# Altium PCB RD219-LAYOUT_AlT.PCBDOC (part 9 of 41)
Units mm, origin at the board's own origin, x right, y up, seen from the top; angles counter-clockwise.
Board outline 209.75 x 159.97 mm, 2 copper layers (TOP, BOTTOM), stack 0 mm thick; 398 components, 199 nets, 1469 pads, 0 vias.
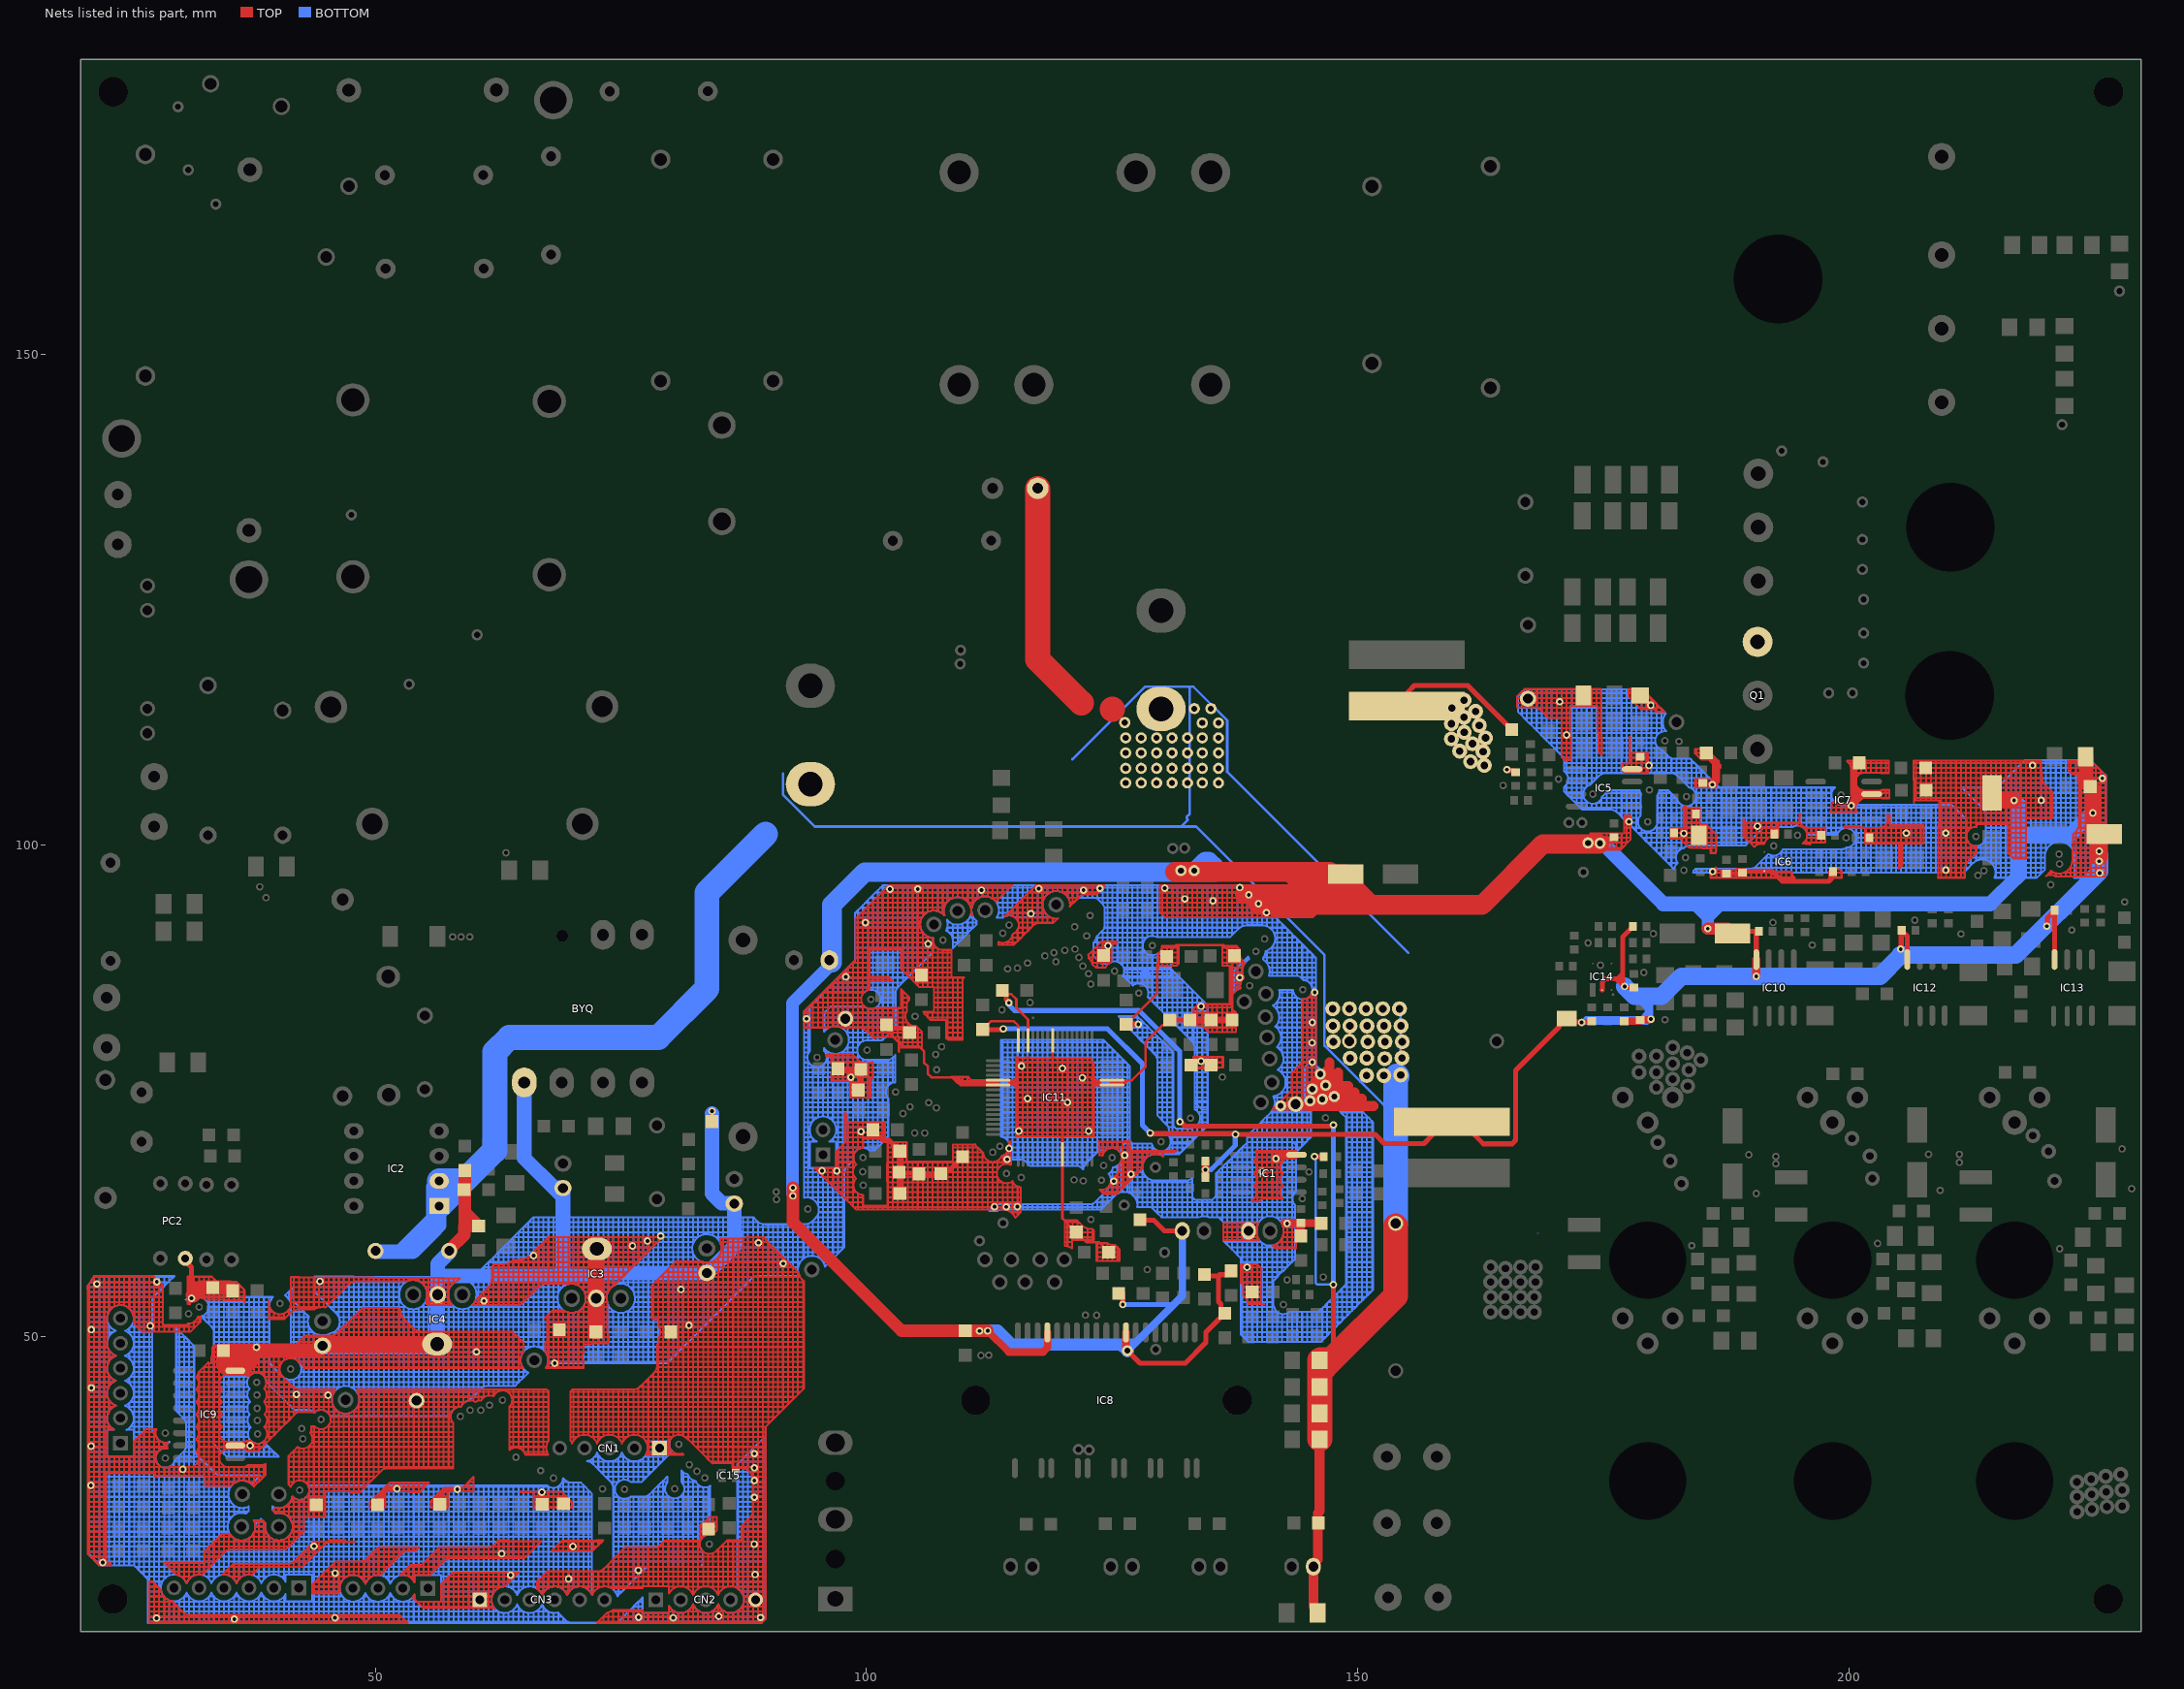
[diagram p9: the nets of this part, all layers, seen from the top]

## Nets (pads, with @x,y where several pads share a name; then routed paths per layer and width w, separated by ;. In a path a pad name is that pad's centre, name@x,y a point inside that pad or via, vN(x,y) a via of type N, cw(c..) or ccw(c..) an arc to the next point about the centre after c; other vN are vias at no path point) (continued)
GND: (continued)
  TOP w0.203: 69.149,48.956 69.657,48.956 ; 69.149,49.464 69.149,49.972 ; 69.149,49.464 69.657,49.464 ; 69.149,49.972 C83.2@69.149,50.48 ; 69.149,49.972 69.657,49.972 ; C83.2@69.149,50.48 69.657,50.48 ; C83.2@69.149,50.48 C83.2@69.149,50.988 ; C83.2@69.149,50.988 69.149,51.496 ; C83.2@69.149,50.988 69.657,50.988 ; 69.149,51.496 69.149,52.004 ; 69.149,51.496 69.657,51.496 ; 69.149,52.004 69.149,52.512 ; 69.149,52.004 69.657,52.004 ; 69.149,52.512 69.149,52.684 ; 69.149,52.512 69.483,52.512 ; 69.149,52.684 69.161,52.684 ; 69.149,55.388 69.657,55.388 ; 69.149,55.388 69.149,55.56 ; 69.149,55.56 69.149,56.068 ; 69.149,55.56 69.657,55.56 ; 69.149,56.068 69.657,56.068 ; 69.149,56.068 69.149,56.576 ; 69.149,56.576 69.657,56.576 ; 69.149,56.576 69.149,57.084 ; 69.149,57.084 69.657,57.084 ; 69.149,57.084 69.149,57.592 ; 69.149,57.592 69.149,58.1 ; 69.149,57.592 69.657,57.592 ; 69.149,58.1 69.149,58.608 ; 69.149,58.1 69.657,58.1 ; 69.149,58.608 69.657,58.608 ; 69.149,58.608 69.149,59.116 ; 69.149,59.116 69.657,59.116 ; 69.149,59.116 69.149,59.624 ; 69.149,59.624 69.657,59.624 ; 69.149,59.624 69.149,60.132 ; 69.149,60.132 69.657,60.132 ; 69.161,52.684 ccw(c69.991,53.846) 69.483,52.512 ; 69.483,52.512 ccw(c69.991,53.846) 69.657,52.458 ; 69.503,33.716 R80.1@69.657,33.562 ; 69.657,23.962 cw(c70.8,23.241) 69.728,24.064 ; 69.657,23.962 69.657,24.064 ; 69.657,24.064 69.657,24.572 ; 69.657,24.064 69.728,24.064 ; 69.657,24.572 pad.@69.657,25.08 ; 69.657,24.572 70.165,24.572 ; pad.@69.657,25.08 pad.@69.657,25.588 ; pad.@69.657,25.08 70.165,25.08 ; pad.@69.657,25.588 69.657,26.096 ; pad.@69.657,25.588 70.165,25.588 ; 69.657,26.096 69.657,26.129 ; 69.657,26.096 70.165,26.096 ; 69.657,26.129 70.165,26.129 ; 69.657,28.222 69.657,28.636 ; 69.657,28.222 70.165,28.222 ; 69.657,28.636 pad.@70.165,28.636 ; 69.657,28.636 69.657,29.144 ; 69.657,29.144 70.165,29.144 ; 69.657,29.144 69.657,29.244 ; R80.1@69.657,32.596 R80.1@69.657,32.7 ; R80.1@69.657,32.596 70.016,32.596 70.016,32.7 ; R80.1@69.657,32.7 70.016,32.7 ; R80.1@69.657,32.7 R80.1@69.657,33.208 ; R80.1@69.657,33.208 70.011,33.208 ; R80.1@69.657,33.208 R80.1@69.657,33.562 ; R80.1@69.657,33.562 70.011,33.208 ; 69.657,46.838 70.165,46.838 ; 69.657,46.838 69.657,46.924 ; 69.657,46.924 70.165,46.924 ; 69.657,46.924 69.657,47.432 ; 69.657,47.432 70.165,47.432 ; 69.657,47.432 69.657,47.94 ; 69.657,47.94 69.657,48.448 ; 69.657,47.94 70.165,47.94 ; 69.657,48.448 69.657,48.956 ; 69.657,48.448 70.165,48.448 ; 69.657,48.956 69.657,49.464 ; 69.657,48.956 70.165,48.956 ; 69.657,49.464 69.657,49.972 ; 69.657,49.464 70.165,49.464 ; 69.657,49.972 69.657,50.48 ; 69.657,49.972 70.165,49.972 ; 69.657,50.48 69.657,50.988 ; 69.657,50.48 70.165,50.48 ; 69.657,50.988 69.657,51.496 ; 69.657,50.988 70.165,50.988 ; 69.657,51.496 69.657,52.004 ; 69.657,51.496 70.165,51.496 ; 69.657,52.004 70.165,52.004 ; 69.657,52.004 69.657,52.458 ; 69.657,52.458 ccw(c69.991,53.846) 70.165,52.429 ; 69.657,55.388 69.657,55.56 ; 69.657,55.388 69.806,55.388 ; 69.657,55.56 69.657,56.068 ; 69.657,55.56 70.165,55.56 ; 69.657,56.068 69.657,56.576 ; 69.657,56.068 70.165,56.068 ; 69.657,56.576 70.165,56.576 ; 69.657,56.576 69.657,57.084 ; 69.657,57.084 70.165,57.084 ; 69.657,57.084 69.657,57.592 ; 69.657,57.592 69.657,58.1 ; 69.657,57.592 70.165,57.592 ; 69.657,58.1 69.657,58.608 ; 69.657,58.1 70.165,58.1 ; 69.657,58.608 69.657,59.116 ; 69.657,58.608 70.165,58.608 ; 69.657,59.116 69.657,59.624 ; 69.657,59.116 70.165,59.116 ; 69.657,59.624 69.657,60.132 ; 69.657,59.624 70.165,59.624 ; 69.657,60.132 70.165,60.132 ; 69.728,24.064 cw(c70.8,23.241) 70.165,24.434 ; 69.806,55.388 cw(c69.991,53.973) 69.817,55.389 cw(c69.991,53.973) 70.165,55.389 ; 69.87,39.812 70.165,39.812 ; 69.87,39.812 69.87,40.32 ; 69.87,40.32 70.165,40.32 ; 69.87,40.32 69.87,40.828 ; 69.87,40.828 70.165,40.828 ; 69.87,40.828 69.87,41.336 ; 69.87,41.336 70.165,41.336 ; 69.87,41.336 69.87,41.844 ; 69.87,41.844 70.165,41.844 ; 69.87,41.844 69.87,42.352 ; 69.87,42.352 70.165,42.352 ; 69.87,42.352 69.87,42.86 ; 69.87,42.86 70.165,42.86 ; 69.87,42.86 69.87,43.368 ; 69.87,43.368 70.165,43.368 ; 69.87,43.368 69.87,43.876 ; 69.87,43.876 69.87,44.384 ; 69.87,43.876 70.165,43.876 ; 69.87,44.384 70.165,44.384 ; 69.87,44.384 69.87,44.436 70.069,44.635 70.165,44.635 ; 69.961,39.304 cw(c68.768,38.669) 70.038,39.132 cw(c71.308,38.669) 70.115,39.304 ; 69.961,39.304 70.115,39.304 ; 70.011,33.208 70.016,33.203 70.016,32.7 ; 70.115,39.304 cw(c71.308,38.669) 70.165,39.39 ; 70.165,24.434 cw(c70.8,23.241) 70.565,24.572 ; 70.165,24.434 70.165,24.572 ; 70.165,24.572 70.165,25.08 ; 70.165,24.572 70.565,24.572 ; 70.165,25.08 70.673,25.08 ; 70.165,25.08 70.165,25.588 ; 70.165,25.588 70.165,26.096 ; 70.165,25.588 70.673,25.588 ; 70.165,26.096 70.165,26.129 ; 70.165,26.096 70.673,26.096 ; 70.165,26.129 70.673,26.129 ; 70.165,28.222 pad.@70.165,28.636 ; 70.165,28.222 70.673,28.222 ; pad.@70.165,28.636 70.673,28.636 ; pad.@70.165,28.636 70.165,29.144 ; 70.165,29.144 70.165,29.241 ; 70.165,29.144 70.673,29.144 ; 70.165,29.241 70.673,29.241 ; 70.165,39.39 cw(c71.308,38.669) 70.587,39.812 ; 70.165,39.39 70.165,39.812 ; 70.165,39.812 70.165,40.32 ; 70.165,39.812 70.587,39.812 ; 70.165,40.32 70.165,40.828 ; 70.165,40.32 70.673,40.32 ; 70.165,40.828 70.165,41.336 ; 70.165,40.828 70.673,40.828 ; 70.165,41.336 70.165,41.844 ; 70.165,41.336 70.673,41.336 ; 70.165,41.844 70.165,42.352 ; 70.165,41.844 70.673,41.844 ; 70.165,42.352 70.165,42.86 ; 70.165,42.352 70.673,42.352 ; 70.165,42.86 70.165,43.368 ; 70.165,42.86 70.673,42.86 ; 70.165,43.368 70.165,43.876 ; 70.165,43.368 70.673,43.368 ; 70.165,43.876 70.165,44.384 ; 70.165,43.876 70.673,43.876 ; 70.165,44.384 70.165,44.635 ; 70.165,44.384 70.673,44.384 ; 70.165,44.635 70.673,44.635 ; 70.165,46.838 70.165,46.924 ; 70.165,46.838 70.673,46.838 ; 70.165,46.924 70.165,47.432 ; 70.165,46.924 70.673,46.924 ; 70.165,47.432 70.165,47.94 ; 70.165,47.432 70.673,47.432 ; 70.165,47.94 70.165,48.448 ; 70.165,47.94 70.673,47.94 ; 70.165,48.448 70.165,48.956 ; 70.165,48.448 70.673,48.448 ; 70.165,48.956 70.165,49.464 ; 70.165,48.956 70.673,48.956 ; 70.165,49.464 70.165,49.972 ; 70.165,49.464 70.673,49.464 ; 70.165,49.972 70.165,50.48 ; 70.165,49.972 70.673,49.972 ; 70.165,50.48 70.165,50.988 ; 70.165,50.48 70.673,50.48 ; 70.165,50.988 70.165,51.496 ; 70.165,50.988 70.673,50.988 ; 70.165,51.496 70.165,52.004 ; 70.165,51.496 70.673,51.496 ; 70.165,52.004 70.673,52.004 ; 70.165,52.004 70.165,52.429 ; 70.165,52.429 ccw(c69.991,53.846) 70.499,52.512 ; 70.165,55.389 cw(c69.991,53.973) 70.673,55.226 ; 70.165,55.389 70.165,55.56 ; 70.165,55.56 70.165,56.068 ; 70.165,55.56 70.673,55.56 ; 70.165,56.068 70.165,56.576 ; 70.165,56.068 70.673,56.068 ; 70.165,56.576 70.165,57.084 ; 70.165,56.576 70.673,56.576 ; 70.165,57.084 70.165,57.592 ; 70.165,57.084 70.673,57.084 ; 70.165,57.592 70.165,58.1 ; 70.165,57.592 70.673,57.592 ; 70.165,58.1 70.165,58.608 ; 70.165,58.1 70.673,58.1 ; 70.165,58.608 70.165,59.116 ; 70.165,58.608 70.673,58.608 ; 70.165,59.116 70.165,59.624 ; 70.165,59.116 70.673,59.116 ; 70.165,59.624 70.165,60.132 ; 70.165,59.624 70.673,59.624 ; 70.165,60.132 70.673,60.132 ; 70.499,52.512 ccw(c69.991,53.846) 70.502,52.513 ccw(c69.991,53.846) 70.673,52.592 ; 70.499,52.512 70.673,52.512 ; 70.565,24.572 cw(c70.8,23.241) 70.673,24.587 ; 70.587,39.812 cw(c71.308,38.669) 70.592,39.815 cw(c71.308,38.669) 70.673,39.862 ; 70.673,24.587 cw(c70.8,23.241) 71.035,24.572 ; 70.673,24.587 70.673,25.08 ; 70.673,25.08 71.181,25.08 ; 70.673,25.08 70.673,25.588 ; 70.673,25.588 70.673,26.096 ; 70.673,25.588 71.181,25.588 ; 70.673,26.096 71.181,26.096 ; 70.673,26.096 70.673,26.129 ; 70.673,26.129 71.181,26.129 ; 70.673,28.222 70.673,28.636 ; 70.673,28.222 71.181,28.222 ; 70.673,28.636 70.673,29.144 ; 70.673,28.636 71.181,28.636 ; 70.673,29.144 70.673,29.241 ; 70.673,29.144 71.181,29.144 ; 70.673,29.241 71.181,29.241 ; 70.673,39.862 cw(c71.308,38.669) 71.181,40.015 ; 70.673,39.862 70.673,40.32 ; 70.673,40.32 70.673,40.828 ; 70.673,40.32 71.181,40.32 ; 70.673,40.828 70.673,41.336 ; 70.673,40.828 71.181,40.828 ; 70.673,41.336 70.673,41.844 ; 70.673,41.336 71.181,41.336 ; 70.673,41.844 70.673,42.352 ; 70.673,41.844 71.181,41.844 ; 70.673,42.352 70.673,42.86 ; 70.673,42.352 71.181,42.352 ; 70.673,42.86 70.673,43.368 ; 70.673,42.86 71.181,42.86 ; 70.673,43.368 70.673,43.876 ; 70.673,43.368 71.181,43.368 ; 70.673,43.876 70.673,44.384 ; 70.673,43.876 71.181,43.876 ; 70.673,44.384 70.673,44.635 ; 70.673,44.384 71.181,44.384 ; 70.673,44.635 71.181,44.635 ; 70.673,46.838 71.181,46.838 ; 70.673,46.838 70.673,46.924 ; 70.673,46.924 71.181,46.924 ; 70.673,46.924 70.673,47.432 ; 70.673,47.432 71.181,47.432 ; 70.673,47.432 70.673,47.94 ; 70.673,47.94 70.673,48.448 ; 70.673,47.94 71.1,47.94 ; 70.673,48.448 70.673,48.956 ; 70.673,48.448 71.179,48.448 ; 70.673,48.956 70.673,49.464 ; 70.673,48.956 71.181,48.956 ; 70.673,49.464 71.181,49.464 ; 70.673,49.464 70.673,49.972 ; 70.673,49.972 71.181,49.972 ; 70.673,49.972 70.673,50.48 ; 70.673,50.48 71.181,50.48 ; 70.673,50.48 70.673,50.988 ; 70.673,50.988 70.673,51.496 ; 70.673,50.988 71.181,50.988 ; 70.673,51.496 70.673,52.004 ; 70.673,51.496 71.181,51.496 ; 70.673,52.004 71.181,52.004 ; 70.673,52.004 70.673,52.512 ; 70.673,52.512 71.181,52.512 ; 70.673,52.512 70.673,52.592 ; 70.673,52.592 ccw(c69.991,53.846) 71.155,53.02 ; 70.673,55.226 cw(c69.991,53.973) 70.683,55.221 cw(c69.991,53.973) 70.924,55.052 ; 70.673,55.226 70.673,55.56 ; 70.673,55.56 70.673,56.068 ; 70.673,55.56 71.181,55.56 ; 70.673,56.068 70.673,56.576 ; 70.673,56.068 71.181,56.068 ; 70.673,56.576 70.673,57.084 ; 70.673,56.576 71.181,56.576 ; 70.673,57.084 70.673,57.592 ; 70.673,57.084 71.181,57.084 ; 70.673,57.592 70.673,58.1 ; 70.673,57.592 71.181,57.592 ; 70.673,58.1 70.673,58.608 ; 70.673,58.1 71.181,58.1 ; 70.673,58.608 70.673,59.116 ; 70.673,58.608 IC3.4@71.181,58.608 ; 70.673,59.116 70.673,59.624 ; 70.673,59.116 IC3.4@71.181,59.116 ; 70.673,59.624 70.673,60.132 ; 70.673,59.624 71.181,59.624 ; 70.673,60.132 71.181,60.132 ; 70.924,55.052 cw(c69.991,53.973) 71.174,54.771 cw(c69.991,53.973) 71.181,54.76 ; 70.924,55.052 71.181,55.052 ; 71.035,24.572 cw(c70.8,23.241) 71.181,24.538 ; 71.035,24.572 71.181,24.572 ; 71.1,47.94 ccw(c72.451,47.991) 71.181,47.528 ; 71.1,47.94 cw(c72.451,47.991) 71.1,47.944 cw(c72.451,47.991) 71.179,48.448 ; 71.155,53.02 ccw(c69.991,53.846) 71.181,53.058 ; 71.155,53.02 71.181,53.02 ; 71.179,48.448 cw(c72.451,47.991) 71.181,48.453 ; 71.181,24.538 cw(c70.8,23.241) 71.687,24.261 cw(c70.8,23.241) 71.689,24.259 ; 71.181,24.538 71.181,24.572 ; 71.181,24.572 71.689,24.572 ; 71.181,24.572 71.181,25.08 ; 71.181,25.08 71.689,25.08 ; 71.181,25.08 71.181,25.588 ; 71.181,25.588 71.181,26.096 ; 71.181,25.588 71.689,25.588 ; 71.181,26.096 71.689,26.096 ; 71.181,26.096 71.181,26.129 ; 71.181,26.129 71.689,26.129 ; 71.181,28.222 71.181,28.636 ; 71.181,28.222 71.689,28.222 ; 71.181,28.636 71.181,29.144 ; 71.181,28.636 71.689,28.636 ; 71.181,29.144 71.181,29.241 ; 71.181,29.144 71.689,29.144 ; 71.181,29.241 71.689,29.241 ; 71.181,40.015 cw(c71.308,38.669) 71.681,39.968 cw(c71.308,38.669) 71.689,39.966 ; 71.181,40.015 71.181,40.32 ; 71.181,40.32 71.181,40.828 ; 71.181,40.32 71.689,40.32 ; 71.181,40.828 71.181,41.336 ; 71.181,40.828 71.689,40.828 ; 71.181,41.336 71.181,41.844 ; 71.181,41.336 71.689,41.336 ; 71.181,41.844 71.181,42.352 ; 71.181,41.844 71.689,41.844 ; 71.181,42.352 71.181,42.86 ; 71.181,42.352 71.689,42.352 ; 71.181,42.86 71.181,43.368 ; 71.181,42.86 71.689,42.86 ; 71.181,43.368 71.181,43.876 ; 71.181,43.368 71.689,43.368 ; 71.181,43.876 71.181,44.384 ; 71.181,43.876 71.689,43.876 ; 71.181,44.384 71.181,44.635 ; 71.181,44.384 71.689,44.384 ; 71.181,44.635 71.689,44.635 ; 71.181,46.838 71.181,46.924 ; 71.181,46.838 71.199,46.838 71.199,46.924 ; 71.181,46.924 71.199,46.924 ; 71.181,46.924 71.181,47.432 ; 71.181,47.432 71.199,47.432 ; 71.181,47.432 71.181,47.528 ; 71.181,48.453 71.181,48.956 ; 71.181,48.956 71.181,49.464 ; 71.181,48.956 71.199,48.956 ; 71.181,49.464 71.181,49.972 ; 71.181,49.464 71.689,49.464 ; 71.181,49.972 71.181,50.48 ; 71.181,49.972 71.689,49.972 ; 71.181,50.48 71.689,50.48 ; 71.181,50.48 71.181,50.988 ; 71.181,50.988 71.181,51.496 ; 71.181,50.988 71.689,50.988 ; 71.181,51.496 71.181,52.004 ; 71.181,51.496 71.689,51.496 ; 71.181,52.004 71.689,52.004 ; 71.181,52.004 71.181,52.512 ; 71.181,52.512 71.181,53.02 ; 71.181,52.512 71.689,52.512 ; 71.181,53.02 71.689,53.02 ; 71.181,53.02 71.181,53.058 ; 71.181,53.058 ccw(c69.991,53.846) 71.382,53.528 ; 71.181,54.76 cw(c69.991,53.973) 71.295,54.553 cw(c69.991,53.973) 71.299,54.544 ; 71.181,54.76 71.181,55.052 ; 71.181,55.052 71.181,55.56 ; 71.181,55.052 71.689,55.052 ; 71.181,55.56 71.181,56.068 ; 71.181,55.56 71.689,55.56 ; 71.181,56.068 71.181,56.576 ; 71.181,56.068 71.689,56.068 ; 71.181,56.576 71.181,57.084 ; 71.181,56.576 71.689,56.576 ; 71.181,57.084 71.181,57.592 ; 71.181,57.084 71.689,57.084 ; 71.181,57.592 71.181,58.1 ; 71.181,57.592 71.689,57.592 ; 71.181,58.1 IC3.4@71.181,58.608 ; 71.181,58.1 IC3.4@71.689,58.1 ; IC3.4@71.181,58.608 IC3.4@71.689,58.608 ; IC3.4@71.181,58.608 IC3.4@71.181,59.116 ; IC3.4@71.181,59.116 71.181,59.624 ; IC3.4@71.181,59.116 IC3.4@71.689,59.116 ; 71.181,59.624 71.181,60.132 ; 71.181,59.624 IC3.4@71.689,59.624 ; 71.181,60.132 71.689,60.132 ; 71.199,46.924 71.199,47.432 ; 71.199,48.956 71.199,49.242 71.689,49.242 ; 71.299,54.544 cw(c69.991,53.973) 71.417,54.036 ; 71.299,54.544 71.689,54.544 ; 71.382,53.528 ccw(c69.991,53.846) 71.418,53.846 71.418,53.973 ccw(c69.991,53.973) 71.417,54.036 ; 71.382,53.528 71.689,53.528 ; 71.417,54.036 IC3.2@71.689,54.036 ; 71.689,24.259 71.689,24.572 ; 71.689,24.572 71.689,25.08 ; 71.689,24.572 72.197,24.572 ; 71.689,25.08 71.689,25.588 ; 71.689,25.08 72.197,25.08 ; 71.689,25.588 71.689,26.096 ; 71.689,25.588 72.197,25.588 ; 71.689,26.096 71.689,26.129 ; 71.689,26.096 72.197,26.096 ; 71.689,26.129 72.197,26.129 ; 71.689,28.222 71.689,28.636 ; 71.689,28.222 72.149,28.222 72.197,28.269 ; 71.689,28.636 72.197,28.636 ; 71.689,28.636 71.689,29.144 ; 71.689,29.144 72.197,29.144 ; 71.689,29.144 71.689,29.241 ; 71.689,29.241 72.197,29.241 ; 71.689,39.966 cw(c71.308,38.669) 72.024,39.815 cw(c71.308,38.669) 72.029,39.812 ; 71.689,39.966 71.689,40.32 ; 71.689,40.32 71.689,40.828 ; 71.689,40.32 72.197,40.32 ; 71.689,40.828 71.689,41.336 ; 71.689,40.828 72.197,40.828 ; 71.689,41.336 71.689,41.844 ; 71.689,41.336 72.197,41.336 ; 71.689,41.844 71.689,42.352 ; 71.689,41.844 72.197,41.844 ; 71.689,42.352 71.689,42.86 ; 71.689,42.352 72.197,42.352 ; 71.689,42.86 71.689,43.368 ; 71.689,42.86 72.197,42.86 ; 71.689,43.368 71.689,43.876 ; 71.689,43.368 72.197,43.368 ; 71.689,43.876 71.689,44.384 ; 71.689,43.876 72.197,43.876 ; 71.689,44.384 71.689,44.635 ; 71.689,44.384 72.197,44.384 ; 71.689,44.635 72.197,44.635 ; 71.689,49.242 71.689,49.464 ; 71.689,49.464 71.689,49.972 ; 71.689,49.464 72.197,49.464 ; 71.689,49.972 71.689,50.48 ; 71.689,49.972 R136.2@72.197,49.972 ; 71.689,50.48 71.689,50.988 ; 71.689,50.48 R136.2@72.197,50.48 ; 71.689,50.988 71.689,51.496 ; 71.689,50.988 R136.2@72.197,50.988 ; 71.689,51.496 71.689,52.004 ; 71.689,51.496 72.197,51.496 ; 71.689,52.004 71.689,52.512 ; 71.689,52.004 72.197,52.004 ; 71.689,52.512 71.689,53.02 ; 71.689,52.512 72.197,52.512 ; 71.689,53.02 71.689,53.528 ; 71.689,53.02 72.197,53.02 ; 71.689,53.528 IC3.2@72.197,53.528 ; 71.689,53.528 IC3.2@71.689,54.036 ; IC3.2@71.689,54.036 71.689,54.544 ; IC3.2@71.689,54.036 IC3.2@72.197,54.036 ; 71.689,54.544 71.689,55.052 ; 71.689,54.544 IC3.2@72.197,54.544 ; 71.689,55.052 71.689,55.56 ; 71.689,55.052 72.197,55.052 ; 71.689,55.56 71.689,56.068 ; 71.689,55.56 72.197,55.56 ; 71.689,56.068 71.689,56.576 ; 71.689,56.068 72.197,56.068 ; 71.689,56.576 71.689,57.084 ; 71.689,56.576 72.197,56.576 ; 71.689,57.084 71.689,57.592 ; 71.689,57.084 72.197,57.084 ; 71.689,57.592 IC3.4@71.689,58.1 ; 71.689,57.592 72.197,57.592 ; IC3.4@71.689,58.1 IC3.4@71.689,58.608 ; IC3.4@71.689,58.1 IC3.4@72.197,58.1 ; IC3.4@71.689,58.608 IC3.4@72.197,58.608 ; IC3.4@71.689,58.608 IC3.4@71.689,59.116 ; IC3.4@71.689,59.116 IC3.4@71.689,59.624 ; IC3.4@71.689,59.116 IC3.4@72.197,59.116 ; IC3.4@71.689,59.624 71.689,60.132 ; IC3.4@71.689,59.624 IC3.4@72.197,59.624 ; 71.689,60.132 72.197,60.132 ; 72.029,39.812 cw(c71.308,38.669) 72.195,39.689 cw(c71.308,38.669) 72.197,39.687 ; 72.029,39.812 72.197,39.812 ; 72.197,24.064 72.197,24.572 ; 72.197,24.064 72.268,24.064 ; 72.197,24.572 72.705,24.572 ; 72.197,24.572 72.197,25.08 ; 72.197,25.08 72.705,25.08 ; 72.197,25.08 72.197,25.588 ; 72.197,25.588 72.197,26.096 ; 72.197,25.588 72.705,25.588 ; 72.197,26.096 72.705,26.096 ; 72.197,26.096 72.197,26.129 ; 72.197,26.129 72.705,26.129 ; 72.197,28.269 72.564,28.636 ; 72.197,28.269 72.197,28.636 ; 72.197,28.636 72.197,29.144 ; 72.197,28.636 72.564,28.636 ; 72.197,29.144 72.197,29.241 ; 72.197,29.144 72.705,29.144 ; 72.197,39.687 cw(c71.308,38.669) 72.501,39.304 ; 72.197,39.687 72.197,39.812 ; 72.197,39.812 72.197,40.32 ; 72.197,39.812 72.705,39.812 ; 72.197,40.32 72.197,40.828 ; 72.197,40.32 72.705,40.32 ; 72.197,40.828 72.197,41.336 ; 72.197,40.828 72.705,40.828 ; 72.197,41.336 72.197,41.844 ; 72.197,41.336 72.705,41.336 ; 72.197,41.844 72.197,42.352 ; 72.197,41.844 72.705,41.844 ; 72.197,42.352 72.197,42.86 ; 72.197,42.352 72.705,42.352 ; 72.197,42.86 72.197,43.368 ; 72.197,42.86 72.705,42.86 ; 72.197,43.368 72.197,43.876 ; 72.197,43.368 72.705,43.368 ; 72.197,43.876 72.197,44.384 ; 72.197,43.876 72.705,43.876 ; 72.197,44.384 72.705,44.384 ; 72.197,44.384 72.197,44.635 ; 72.197,44.635 72.705,44.635 ; 72.197,49.318 cw(c72.451,47.991) 72.451,49.342 72.705,49.342 ; 72.197,49.318 72.197,49.464 ; 72.197,49.464 R136.2@72.197,49.972 ; 72.197,49.464 72.705,49.464 ; R136.2@72.197,49.972 R136.2@72.197,50.48 ; R136.2@72.197,49.972 R136.2@72.705,49.972 ; R136.2@72.197,50.48 R136.2@72.451,50.48 R136.2@72.705,50.48 ; R136.2@72.197,50.48 R136.2@72.197,50.988 ; R136.2@72.197,50.988 72.197,51.496 ; R136.2@72.197,50.988 72.462,50.988 R136.2@72.705,50.988 ; 72.197,51.496 72.462,51.496 72.705,51.496 ; 72.197,51.496 72.197,52.004 ; 72.197,52.004 72.197,52.512 ; 72.197,52.004 72.462,52.004 72.705,52.004 ; 72.197,52.512 72.462,52.512 72.705,52.512 ; 72.197,52.512 72.197,53.02 ; 72.197,53.02 IC3.2@72.197,53.528 ; 72.197,53.02 72.462,53.02 72.705,53.02 ; IC3.2@72.197,53.528 72.462,53.528 IC3.2@72.705,53.528 ; IC3.2@72.197,53.528 IC3.2@72.197,54.036 ; IC3.2@72.197,54.036 IC3.2@72.197,54.544 ; IC3.2@72.197,54.036 72.52,54.036 IC3.2@72.705,54.036 ; IC3.2@72.197,54.544 72.197,55.052 ; IC3.2@72.197,54.544 72.52,54.544 IC3.2@72.705,54.544 ; 72.197,55.052 72.52,55.052 72.705,55.052 ; 72.197,55.052 72.197,55.56 ; 72.197,55.56 72.197,56.068 ; 72.197,55.56 72.52,55.56 72.705,55.56 ; 72.197,56.068 72.52,56.068 72.705,56.068 ; 72.197,56.068 72.197,56.576 ; 72.197,56.576 72.197,57.084 ; 72.197,56.576 72.52,56.576 72.705,56.576 ; 72.197,57.084 72.52,57.084 72.705,57.084 ; 72.197,57.084 72.197,57.592 ; 72.197,57.592 IC3.4@72.197,58.1 ; 72.197,57.592 72.52,57.592 72.705,57.592 ; IC3.4@72.197,58.1 72.52,58.1 IC3.4@72.705,58.1 ; IC3.4@72.197,58.1 IC3.4@72.197,58.608 ; IC3.4@72.197,58.608 72.52,58.608 IC3.4@72.705,58.608 ; IC3.4@72.197,58.608 IC3.4@72.197,59.116 ; IC3.4@72.197,59.116 IC3.4@72.197,59.624 ; IC3.4@72.197,59.116 IC3.4@72.705,59.116 ; IC3.4@72.197,59.624 72.197,60.132 ; IC3.4@72.197,59.624 IC3.4@72.705,59.624 ; 72.197,60.132 72.705,60.132 ; 72.268,24.064 cw(c73.34,23.241) 72.705,24.434 ; 72.501,39.304 cw(c71.308,38.669) 72.578,39.132 cw(c73.848,38.669) 72.655,39.304 ; 72.501,39.304 72.655,39.304 ; 72.564,28.636 72.705,28.777 ; 72.655,39.304 cw(c73.848,38.669) 72.705,39.39 ; 72.701,21.016 72.705,21.02 ; 72.701,21.016 72.574,20.889 72.705,20.889 ; 72.701,21.016 72.705,21.016 ; 72.705,20.889 72.705,21.016 ; 72.705,20.889 73.213,20.889 ; 72.705,21.016 73.213,21.016 ; 72.705,21.016 72.705,21.02 ; 72.705,21.02 73.209,21.524 ; 72.705,24.434 cw(c73.34,23.241) 73.105,24.572 ; 72.705,24.434 72.705,24.572 ; 72.705,24.572 72.705,25.08 ; 72.705,24.572 73.105,24.572 ; 72.705,25.08 73.213,25.08 ; 72.705,25.08 72.705,25.588 ; 72.705,25.588 72.705,26.096 ; 72.705,25.588 73.213,25.588 ; 72.705,26.096 73.213,26.096 ; 72.705,26.096 72.705,26.129 ; 72.705,26.129 ccw(c72.705,26.858) 73.213,26.336 ; 72.705,26.129 ccw(c72.705,26.858) 73.213,26.336 ; 72.705,28.777 72.705,29.144 ; 72.705,28.777 73.072,29.144 ; 72.705,29.144 72.705,29.289 ; 72.705,29.144 73.072,29.144 ; 72.705,29.289 73.217,29.289 73.072,29.144 ; 72.705,39.39 cw(c73.848,38.669) 73.127,39.812 ; 72.705,39.39 72.705,39.812 ; 72.705,39.812 72.705,40.32 ; 72.705,39.812 73.127,39.812 ; 72.705,40.32 72.705,40.828 ; 72.705,40.32 73.213,40.32 ; 72.705,40.828 72.705,41.336 ; 72.705,40.828 73.213,40.828 ; 72.705,41.336 72.705,41.844 ; 72.705,41.336 73.213,41.336 ; 72.705,41.844 72.705,42.352 ; 72.705,41.844 73.213,41.844 ; 72.705,42.352 72.705,42.86 ; 72.705,42.352 73.213,42.352 ; 72.705,42.86 72.705,43.368 ; 72.705,42.86 73.213,42.86 ; 72.705,43.368 72.705,43.876 ; 72.705,43.368 73.213,43.368 ; 72.705,43.876 72.705,44.384 ; 72.705,43.876 73.213,43.876 ; 72.705,44.384 72.705,44.635 ; 72.705,44.384 73.213,44.384 ; 72.705,44.635 73.213,44.635 ; 72.705,49.342 72.705,49.464 ; 72.705,49.342 73.213,49.342 ; 72.705,49.464 R136.2@72.705,49.972 ; 72.705,49.464 73.213,49.464 ; R136.2@72.705,49.972 73.213,49.972 ; R136.2@72.705,49.972 R136.2@72.705,50.48 ; R136.2@72.705,50.48 73.213,50.48 ; R136.2@72.705,50.48 R136.2@72.705,50.988 ; R136.2@72.705,50.988 72.705,51.496 ; R136.2@72.705,50.988 73.213,50.988 ; 72.705,51.496 72.705,52.004 ; 72.705,51.496 73.213,51.496 ; 72.705,52.004 72.705,52.512 ; 72.705,52.004 73.213,52.004 ; 72.705,52.512 72.705,53.02 ; 72.705,52.512 73.213,52.512 ; 72.705,53.02 IC3.2@72.705,53.528 ; 72.705,53.02 73.213,53.02 ; IC3.2@72.705,53.528 IC3.2@73.213,53.528 ; IC3.2@72.705,53.528 IC3.2@72.705,54.036 ; IC3.2@72.705,54.036 IC3.2@72.705,54.544 ; IC3.2@72.705,54.036 IC3.2@73.213,54.036 ; IC3.2@72.705,54.544 72.705,55.052 ; IC3.2@72.705,54.544 73.213,54.544 ; 72.705,55.052 72.705,55.56 ; 72.705,55.052 73.213,55.052 ; 72.705,55.56 72.705,56.068 ; 72.705,55.56 73.213,55.56 ; 72.705,56.068 72.705,56.576 ; 72.705,56.068 73.213,56.068 ; 72.705,56.576 72.705,57.084 ; 72.705,56.576 73.213,56.576 ; 72.705,57.084 72.705,57.592 ; 72.705,57.084 73.213,57.084 ; 72.705,57.592 IC3.4@72.705,58.1 ; 72.705,57.592 73.213,57.592 ; IC3.4@72.705,58.1 IC3.4@72.705,58.608 ; IC3.4@72.705,58.1 IC3.4@73.213,58.1 ; IC3.4@72.705,58.608 IC3.4@73.213,58.608 ; IC3.4@72.705,58.608 IC3.4@72.705,59.116 ; IC3.4@72.705,59.116 IC3.4@72.705,59.624 ; IC3.4@72.705,59.116 IC3.4@73.213,59.116 ; IC3.4@72.705,59.624 72.705,60.132 ; IC3.4@72.705,59.624 IC3.4@73.213,59.624 ; 72.705,60.132 73.213,60.132 ; 73.105,24.572 cw(c73.34,23.241) 73.213,24.587 ; 73.127,39.812 cw(c73.848,38.669) 73.132,39.815 cw(c73.848,38.669) 73.213,39.862 ; 73.209,21.524 73.213,21.524 ; 73.209,21.524 73.213,21.528 ; 73.213,20.889 73.721,20.889 ; 73.213,20.889 73.213,21.016 ; 73.213,21.016 73.721,21.016 ; 73.213,21.016 73.213,21.524 ; 73.213,21.524 73.721,21.524 ; 73.213,21.524 73.213,21.528 ; 73.213,21.528 73.599,21.914 ccw(c73.34,23.241) 73.721,21.944 ; 73.213,24.587 cw(c73.34,23.241) 73.575,24.572 ; 73.213,24.587 73.213,25.08 ; 73.213,25.08 73.213,25.588 ; 73.213,25.08 73.721,25.08 ; 73.213,25.588 73.213,26.096 ; 73.213,25.588 73.721,25.588 ; 73.213,26.096 73.721,26.096 ; 73.213,26.096 73.213,26.336 ; 73.213,26.336 ccw(c72.705,26.858) 73.22,26.343 ; 73.213,26.336 ccw(c72.705,26.858) 73.22,26.343 ; 73.213,39.862 cw(c73.848,38.669) 73.721,40.015 ; 73.213,39.862 73.213,40.32 ; 73.213,40.32 73.213,40.828 ; 73.213,40.32 73.721,40.32 ; 73.213,40.828 73.213,41.336 ; 73.213,40.828 73.721,40.828 ; 73.213,41.336 73.213,41.844 ; 73.213,41.336 73.721,41.336 ; 73.213,41.844 73.213,42.352 ; 73.213,41.844 73.721,41.844 ; 73.213,42.352 73.213,42.86 ; 73.213,42.352 73.721,42.352 ; 73.213,42.86 73.213,43.368 ; 73.213,42.86 73.721,42.86 ; 73.213,43.368 73.213,43.876 ; 73.213,43.368 73.721,43.368 ; 73.213,43.876 73.213,44.384 ; 73.213,43.876 73.721,43.876 ; 73.213,44.384 73.213,44.635 ; 73.213,44.384 73.721,44.384 ; 73.213,44.635 73.721,44.635 ; 73.213,49.342 73.721,49.342 ; 73.213,49.342 73.213,49.464 ; 73.213,49.464 73.721,49.464 ; 73.213,49.464 73.213,49.972 ; 73.213,49.972 73.721,49.972 ; 73.213,49.972 73.213,50.48 ; 73.213,50.48 73.213,50.988 ; 73.213,50.48 73.639,50.48 ; 73.213,50.988 73.213,51.496 ; 73.213,50.988 73.639,50.988 ; 73.213,51.496 73.213,52.004 ; 73.213,51.496 73.639,51.496 ; 73.213,52.004 73.213,52.512 ; 73.213,52.004 73.639,52.004 ; 73.213,52.512 73.213,53.02 ; 73.213,52.512 73.639,52.512 ; 73.213,53.02 IC3.2@73.213,53.528 ; 73.213,53.02 73.639,53.02 ; IC3.2@73.213,53.528 73.6,53.528 ; IC3.2@73.213,53.528 IC3.2@73.213,54.036 ; IC3.2@73.213,54.036 73.213,54.544 ; IC3.2@73.213,54.036 73.565,54.036 ; 73.213,54.544 73.213,55.052 ; 73.213,54.544 73.683,54.544 ; 73.213,55.052 73.213,55.56 ; 73.213,55.052 73.721,55.052 ; 73.213,55.56 73.213,56.068 ; 73.213,55.56 73.721,55.56 ; 73.213,56.068 73.213,56.576 ; 73.213,56.068 73.721,56.068 ; 73.213,56.576 73.213,57.084 ; 73.213,56.576 73.721,56.576 ; 73.213,57.084 73.213,57.592 ; 73.213,57.084 73.721,57.084 ; 73.213,57.592 IC3.4@73.213,58.1 ; 73.213,57.592 73.721,57.592 ; IC3.4@73.213,58.1 IC3.4@73.213,58.608 ; IC3.4@73.213,58.1 73.721,58.1 ; IC3.4@73.213,58.608 IC3.4@73.721,58.608 ; IC3.4@73.213,58.608 IC3.4@73.213,59.116 ; IC3.4@73.213,59.116 IC3.4@73.213,59.624 ; IC3.4@73.213,59.116 IC3.4@73.721,59.116 ; IC3.4@73.213,59.624 73.213,60.132 ; IC3.4@73.213,59.624 IC3.4@73.721,59.624 ; 73.213,60.132 73.721,60.132 ; 73.22,26.343 73.481,26.604 ; 73.481,26.604 73.721,26.604 ; 73.481,26.604 73.989,27.112 ; 73.565,54.036 ccw(c74.991,53.973) 73.564,53.973 73.564,53.846 ccw(c74.991,53.846) 73.6,53.528 ; 73.565,54.036 cw(c74.991,53.973) 73.683,54.544 ; 73.575,24.572 cw(c73.34,23.241) 73.721,24.538 ; 73.575,24.572 73.721,24.572 ; 73.6,53.528 ccw(c74.991,53.846) 73.639,53.387 ; 73.639,50.48 ccw(c74.991,50.48) 73.721,50.018 ; 73.639,50.48 73.639,50.988 ; 73.639,50.988 73.639,51.496 ; 73.639,51.496 73.639,52.004 ; 73.639,52.004 73.639,52.512 ; 73.639,52.512 73.639,53.02 ; 73.639,53.02 73.639,53.387 ; 73.683,54.544 cw(c74.991,53.973) 73.719,54.62 cw(c74.991,53.973) 73.721,54.623 ; 73.721,20.889 73.721,21.016 ; 73.721,20.889 74.229,20.889 ; 73.721,21.016 73.721,21.524 ; 73.721,21.016 74.229,21.016 ; 73.721,21.524 74.229,21.524 ; 73.721,21.524 73.721,21.944 ; 73.721,21.944 ccw(c73.34,23.241) 73.944,22.032 ; 73.721,24.538 cw(c73.34,23.241) 74.029,24.404 ; 73.721,24.538 73.721,24.572 ; 73.721,24.572 74.229,24.572 ; 73.721,24.572 73.721,25.08 ; 73.721,25.08 74.229,25.08 ; 73.721,25.08 73.721,25.588 ; 73.721,25.588 73.721,26.096 ; 73.721,25.588 74.229,25.588 ; 73.721,26.096 74.229,26.096 ; 73.721,26.096 73.721,26.604 ; 73.721,26.604 74.229,26.604 ; 73.721,40.015 cw(c73.848,38.669) 74.221,39.968 cw(c73.848,38.669) 74.229,39.966 ; 73.721,40.015 73.721,40.32 ; 73.721,40.32 73.721,40.828 ; 73.721,40.32 74.229,40.32 ; 73.721,40.828 73.721,41.336 ; 73.721,40.828 74.229,40.828 ; 73.721,41.336 73.721,41.844 ; 73.721,41.336 74.229,41.336 ; 73.721,41.844 73.721,42.352 ; 73.721,41.844 74.229,41.844 ; 73.721,42.352 73.721,42.86 ; 73.721,42.352 74.229,42.352 ; 73.721,42.86 73.721,43.368 ; 73.721,42.86 74.229,42.86 ; 73.721,43.368 73.721,43.876 ; 73.721,43.368 74.229,43.368 ; 73.721,43.876 73.721,44.384 ; 73.721,43.876 74.229,43.876 ; 73.721,44.384 73.721,44.635 ; 73.721,44.384 74.229,44.384 ; 73.721,44.635 74.229,44.635 ; 73.721,49.342 73.721,49.464 ; 73.721,49.342 73.739,49.342 73.739,49.464 ; 73.721,49.464 73.721,49.972 ; 73.721,49.464 73.739,49.464 ; 73.721,49.972 73.721,50.018 ; 73.721,54.623 cw(c74.991,53.973) 74.055,55.05 cw(c74.991,53.972) 74.058,55.052 ; 73.721,54.623 73.721,55.052 ; 73.721,55.052 73.721,55.56 ; 73.721,55.052 74.058,55.052 ; 73.721,55.56 73.721,56.068 ; 73.721,55.56 74.229,55.56 ; 73.721,56.068 74.229,56.068 ; 73.721,56.068 73.721,56.576 ; 73.721,56.576 74.229,56.576 ; 73.721,56.576 73.721,57.084 ; 73.721,57.084 74.229,57.084 ; 73.721,57.084 73.721,57.592 ; 73.721,57.592 73.721,58.1 ; 73.721,57.592 74.229,57.592 ; 73.721,58.1 IC3.4@73.721,58.608 ; 73.721,58.1 74.229,58.1 ; IC3.4@73.721,58.608 74.229,58.608 ; IC3.4@73.721,58.608 IC3.4@73.721,59.116 ; IC3.4@73.721,59.116 74.229,59.116 ; IC3.4@73.721,59.116 IC3.4@73.721,59.624 ; IC3.4@73.721,59.624 74.229,59.624 ; IC3.4@73.721,59.624 73.721,60.132 ; 73.721,60.132 74.229,60.132 ; 73.944,22.032 ccw(c73.34,23.241) 74.203,22.2 ; 73.944,22.032 74.229,22.032 ; 73.989,27.112 74.229,27.112 ; 73.989,27.112 74.497,27.62 ; 74.029,24.404 74.229,24.404 ; 74.058,55.052 cw(c74.991,53.972) 74.229,55.179 ; 74.203,22.2 74.229,22.2 ; 74.229,20.889 74.229,21.016 ; 74.229,20.889 74.737,20.889 ; 74.229,21.016 74.229,21.524 ; 74.229,21.016 74.737,21.016 ; 74.229,21.524 74.229,22.032 ; 74.229,21.524 74.737,21.524 ; 74.229,22.032 74.737,22.032 ; 74.229,22.032 74.229,22.2 ; 74.229,22.2 74.737,22.2 ; 74.229,24.404 74.229,24.572 ; 74.229,24.404 74.737,24.404 ; 74.229,24.572 74.737,24.572 ; 74.229,24.572 74.229,25.08 ; 74.229,25.08 74.737,25.08 ; 74.229,25.08 74.229,25.588 ; 74.229,25.588 74.229,26.096 ; 74.229,25.588 74.737,25.588 ; 74.229,26.096 74.737,26.096 ; 74.229,26.096 74.229,26.604 ; 74.229,26.604 74.229,27.112 ; 74.229,26.604 74.737,26.604 ; 74.229,27.112 74.737,27.112 ; 74.229,39.966 cw(c73.848,38.669) 74.564,39.815 cw(c73.848,38.669) 74.569,39.812 ; 74.229,39.966 74.229,40.32 ; 74.229,40.32 74.229,40.828 ; 74.229,40.32 74.737,40.32 ; 74.229,40.828 74.229,41.336 ; 74.229,40.828 74.737,40.828 ; 74.229,41.336 74.229,41.844 ; 74.229,41.336 74.737,41.336 ; 74.229,41.844 74.229,42.352 ; 74.229,41.844 74.737,41.844 ; 74.229,42.352 74.229,42.86 ; 74.229,42.352 74.737,42.352 ; 74.229,42.86 74.229,43.368 ; 74.229,42.86 74.737,42.86 ; 74.229,43.368 74.229,43.876 ; 74.229,43.368 74.737,43.368 ; 74.229,43.876 74.229,44.384 ; 74.229,43.876 74.737,43.876 ; 74.229,44.384 74.229,44.635 ; 74.229,44.384 74.737,44.384 ; 74.229,44.635 74.737,44.635 ; 74.229,55.179 cw(c74.991,53.972) 74.359,55.252 ; 74.229,55.179 74.229,55.56 ; 74.229,55.56 74.229,56.068 ; 74.229,55.56 74.667,55.56 ; 74.229,56.068 74.229,56.576 ; 74.229,56.068 74.737,56.068 ; 74.229,56.576 74.737,56.576 ; 74.229,56.576 74.229,57.084 ; 74.229,57.084 74.737,57.084 ; 74.229,57.084 74.229,57.592 ; 74.229,57.592 74.229,58.1 ; 74.229,57.592 74.737,57.592 ; 74.229,58.1 74.229,58.608 ; 74.229,58.1 74.737,58.1 ; 74.229,58.608 74.229,59.116 ; 74.229,58.608 74.737,58.608 ; 74.229,59.116 74.229,59.624 ; 74.229,59.116 74.737,59.116 ; 74.229,59.624 74.229,60.132 ; 74.229,59.624 74.737,59.624 ; 74.229,60.132 74.737,60.132 ; 74.359,55.252 74.667,55.56 ; 74.497,27.62 74.737,27.62 ; 74.497,27.62 74.737,27.86 ; 74.569,39.812 cw(c73.848,38.669) 74.735,39.689 cw(c73.848,38.669) 74.737,39.687 ; 74.569,39.812 74.737,39.812 ; 74.667,55.56 74.737,55.63 ; 74.737,20.889 74.737,21.016 ; 74.737,20.889 75.245,20.889 ; 74.737,21.016 74.737,21.524 ; 74.737,21.016 75.245,21.016 ; 74.737,21.524 74.737,22.032 ; 74.737,21.524 75.245,21.524 ; 74.737,22.032 74.737,22.2 ; 74.737,22.032 75.245,22.032 ; 74.737,22.2 75.245,22.2 ; 74.737,24.404 74.737,24.572 ; 74.737,24.404 75.245,24.404 ; 74.737,24.572 74.737,25.08 ; 74.737,24.572 75.245,24.572 ; 74.737,25.08 74.737,25.588 ; 74.737,25.08 75.245,25.08 ; 74.737,25.588 74.737,26.096 ; 74.737,25.588 75.245,25.588 ; 74.737,26.096 74.737,26.604 ; 74.737,26.096 75.245,26.096 ; 74.737,26.604 74.737,27.112 ; 74.737,26.604 75.245,26.604 ; 74.737,27.112 74.737,27.62 ; 74.737,27.112 75.245,27.112 ; 74.737,27.62 74.737,27.86 ; 74.737,27.62 75.245,27.62 ; 74.737,27.86 75.005,28.128 ; 74.737,39.687 cw(c73.848,38.669) 75.041,39.304 ; 74.737,39.687 74.737,39.812 ; 74.737,39.812 74.737,40.32 ; 74.737,39.812 75.245,39.812 ; 74.737,40.32 74.737,40.828 ; 74.737,40.32 75.245,40.32 ; 74.737,40.828 74.737,41.336 ; 74.737,40.828 75.245,40.828 ; 74.737,41.336 74.737,41.844 ; 74.737,41.336 75.245,41.336 ; 74.737,41.844 74.737,42.352 ; 74.737,41.844 75.245,41.844 ; 74.737,42.352 74.737,42.86 ; 74.737,42.352 75.245,42.352 ; 74.737,42.86 74.737,43.368 ; 74.737,42.86 75.245,42.86 ; 74.737,43.368 74.737,43.876 ; 74.737,43.368 75.245,43.368 ; 74.737,43.876 74.737,44.384 ; 74.737,43.876 75.245,43.876 ; 74.737,44.384 75.245,44.384 ; 74.737,44.384 74.737,44.635 ; 74.737,44.635 75.245,44.635 ; 74.737,55.63 74.737,56.068 ; 74.737,55.63 75.175,56.068 ; 74.737,56.068 75.175,56.068 ; 74.737,56.068 74.737,56.576 ; 74.737,56.576 75.245,56.576 ; 74.737,56.576 74.737,57.084 ; 74.737,57.084 75.245,57.084 ; 74.737,57.084 74.737,57.592 ; 74.737,57.592 74.737,58.1 ; 74.737,57.592 75.245,57.592 ; 74.737,58.1 74.737,58.608 ; 74.737,58.1 75.245,58.1 ; 74.737,58.608 75.245,58.608 ; 74.737,58.608 74.737,59.116 ; 74.737,59.116 75.245,59.116 ; 74.737,59.116 74.737,59.624 ; 74.737,59.624 75.245,59.624 ; 74.737,59.624 74.737,60.132 ; 74.737,60.132 75.245,60.132 ; 75.005,28.128 75.245,28.128 ; 75.005,28.128 75.245,28.368 ; 75.041,39.304 cw(c73.848,38.669) 75.118,39.132 cw(c76.388,38.669) 75.195,39.304 ; 75.041,39.304 75.195,39.304 ; 75.175,56.068 75.245,56.138 ; 75.195,39.304 cw(c76.388,38.669) 75.245,39.39 ; 75.245,20.889 75.245,21.016 ; 75.245,20.889 75.753,20.889 ; 75.245,21.016 75.245,21.524 ; 75.245,21.016 75.753,21.016 ; 75.245,21.524 75.245,22.032 ; 75.245,21.524 75.753,21.524 ; 75.245,22.032 75.245,22.2 ; 75.245,22.032 75.753,22.032 ; 75.245,22.2 75.753,22.2 ; 75.245,24.404 75.245,24.572 ; 75.245,24.404 75.753,24.404 ; 75.245,24.572 75.245,25.08 ; 75.245,24.572 75.753,24.572 ; 75.245,25.08 75.245,25.588 ; 75.245,25.08 75.753,25.08 ; 75.245,25.588 75.245,26.096 ; 75.245,25.588 75.753,25.588 ; 75.245,26.096 75.245,26.604 ; 75.245,26.096 75.753,26.096 ; 75.245,26.604 75.245,27.112 ; 75.245,26.604 75.753,26.604 ; 75.245,27.112 75.245,27.62 ; 75.245,27.112 75.753,27.112 ; 75.245,27.62 75.245,28.128 ; 75.245,27.62 75.753,27.62 ; 75.245,28.128 75.245,28.368 ; 75.245,28.128 75.753,28.128 ; 75.245,28.368 75.42,28.542 75.753,28.542 ; 75.245,39.39 cw(c76.388,38.669) 75.667,39.812 ; 75.245,39.39 75.245,39.812 ; 75.245,39.812 75.245,40.32 ; 75.245,39.812 75.667,39.812 ; 75.245,40.32 75.245,40.828 ; 75.245,40.32 75.753,40.32 ; 75.245,40.828 75.245,41.336 ; 75.245,40.828 75.753,40.828 ; 75.245,41.336 75.245,41.844 ; 75.245,41.336 75.753,41.336 ; 75.245,41.844 75.245,42.352 ; 75.245,41.844 75.753,41.844 ; 75.245,42.352 75.245,42.86 ; 75.245,42.352 75.753,42.352 ; 75.245,42.86 75.245,43.368 ; 75.245,42.86 75.753,42.86 ; 75.245,43.368 75.245,43.876 ; 75.245,43.368 75.753,43.368 ; 75.245,43.876 75.245,44.384 ; 75.245,43.876 75.753,43.876 ; 75.245,44.384 75.753,44.384 ; 75.245,44.384 75.245,44.635 ; 75.245,44.635 75.753,44.635 ; 75.245,56.138 75.245,56.576 ; 75.245,56.138 75.683,56.576 ; 75.245,56.576 75.683,56.576 ; 75.245,56.576 75.245,57.084 ; 75.245,57.084 75.753,57.084 ; 75.245,57.084 75.245,57.592 ; 75.245,57.592 75.245,58.1 ; 75.245,57.592 75.753,57.592 ; 75.245,58.1 75.245,58.608 ; 75.245,58.1 75.753,58.1 ; 75.245,58.608 75.245,59.116 ; 75.245,58.608 75.753,58.608 ; 75.245,59.116 75.245,59.624 ; 75.245,59.116 75.753,59.116 ; 75.245,59.624 75.753,59.624 ; 75.245,59.624 75.245,60.132 ; 75.245,60.132 75.753,60.132 ; 75.667,39.812 cw(c76.388,38.669) 75.753,39.862 ; 75.683,56.576 75.753,56.646 ; 75.753,20.889 75.753,21.016 ; 75.753,20.889 76.261,20.889 ; 75.753,21.016 75.753,21.524 ; 75.753,21.016 76.261,21.016 ; 75.753,21.524 75.753,22.032 ; 75.753,21.524 76.261,21.524 ; 75.753,22.032 75.753,22.2 ; 75.753,22.032 76.261,22.032 ; 75.753,22.2 76.261,22.2 ; 75.753,24.404 75.753,24.572 ; 75.753,24.404 76.261,24.404 ; 75.753,24.572 75.753,25.08 ; 75.753,24.572 76.261,24.572 ; 75.753,25.08 75.753,25.588 ; 75.753,25.08 76.261,25.08 ; 75.753,25.588 75.753,26.096 ; 75.753,25.588 76.261,25.588 ; 75.753,26.096 75.753,26.604 ; 75.753,26.096 76.261,26.096 ; 75.753,26.604 75.753,27.112 ; 75.753,26.604 76.261,26.604 ; 75.753,27.112 75.753,27.62 ; 75.753,27.112 76.261,27.112 ; 75.753,27.62 75.753,28.128 ; 75.753,27.62 76.261,27.62 ; 75.753,28.128 75.753,28.542 ; 75.753,28.128 76.261,28.128 ; 75.753,28.542 76.261,28.542 ; 75.753,39.862 cw(c76.388,38.669) 76.261,40.015 ; 75.753,39.862 75.753,40.32 ; 75.753,40.32 75.753,40.828 ; 75.753,40.32 76.261,40.32 ; 75.753,40.828 75.753,41.336 ; 75.753,40.828 76.261,40.828 ; 75.753,41.336 75.753,41.844 ; 75.753,41.336 76.261,41.336 ; 75.753,41.844 75.753,42.352 ; 75.753,41.844 76.261,41.844 ; 75.753,42.352 75.753,42.86 ; 75.753,42.352 76.261,42.352 ; 75.753,42.86 75.753,43.368 ; 75.753,42.86 76.261,42.86 ; 75.753,43.368 75.753,43.876 ; 75.753,43.368 76.261,43.368 ; 75.753,43.876 75.753,44.384 ; 75.753,43.876 76.261,43.876 ; 75.753,44.384 76.261,44.384 ; 75.753,44.384 75.753,44.635 ; 75.753,44.635 76.217,44.635 ; 75.753,56.646 75.753,57.084 ; 75.753,57.084 75.753,57.592 ; 75.753,57.084 76.191,57.084 ; 75.753,57.592 75.753,58.1 ; 75.753,57.592 76.261,57.592 ; 75.753,58.1 75.753,58.608 ; 75.753,58.1 76.261,58.1 ; 75.753,58.608 75.753,59.116 ; 75.753,58.608 76.261,58.608 ; 75.753,59.116 pad.@76.261,59.116 ; 75.753,59.116 75.753,59.624 ; 75.753,59.624 75.753,60.132 ; 75.753,59.624 76.261,59.624 ; 75.753,60.132 76.261,60.132 ; 76.191,57.084 76.261,57.154 ; 76.217,44.635 ccw(c76.217,45.737) 76.261,44.636 ; 76.217,44.635 ccw(c76.217,45.737) 76.261,44.636 ; 76.261,20.889 76.261,21.016 ; 76.261,20.889 76.769,20.889 ; 76.261,21.016 76.261,21.524 ; 76.261,21.016 76.769,21.016 ; 76.261,21.524 76.261,22.032 ; 76.261,21.524 pad.@76.769,21.524 ; 76.261,22.032 76.261,22.2 ; 76.261,22.032 76.769,22.032 ; 76.261,22.2 76.769,22.2 ; 76.261,24.404 76.261,24.572 ; 76.261,24.404 76.769,24.404 ; 76.261,24.572 76.261,25.08 ; 76.261,24.572 76.769,24.572 ; 76.261,25.08 76.261,25.588 ; 76.261,25.08 76.769,25.08 ; 76.261,25.588 76.261,26.096 ; 76.261,25.588 76.769,25.588 ; 76.261,26.096 76.261,26.604 ; 76.261,26.096 pad.@76.769,26.096 ; 76.261,26.604 76.261,27.112 ; 76.261,26.604 76.769,26.604 ; 76.261,27.112 76.261,27.62 ; 76.261,27.112 76.769,27.112 ; 76.261,27.62 76.261,28.128 ; 76.261,27.62 76.769,27.62 ; 76.261,28.128 76.261,28.542 ; 76.261,28.128 76.769,28.128 ; 76.261,28.542 76.769,28.542 ; 76.261,40.015 cw(c76.388,38.669) 76.769,39.966 ; 76.261,40.015 76.261,40.32 ; 76.261,40.32 76.261,40.828 ; 76.261,40.32 76.769,40.32 ; 76.261,40.828 76.261,41.336 ; 76.261,40.828 76.769,40.828 ; 76.261,41.336 76.261,41.844 ; 76.261,41.336 76.769,41.336 ; 76.261,41.844 76.261,42.352 ; 76.261,41.844 76.769,41.844 ; 76.261,42.352 76.261,42.86 ; 76.261,42.352 76.769,42.352 ; 76.261,42.86 76.261,43.368 ; 76.261,42.86 76.769,42.86 ; 76.261,43.368 76.261,43.876 ; 76.261,43.368 76.769,43.368 ; 76.261,43.876 76.261,44.384 ; 76.261,43.876 76.769,43.876 ; 76.261,44.384 76.769,44.384 ; 76.261,44.384 76.261,44.636 ; 76.261,44.636 ccw(c76.217,45.737) 76.769,44.784 ; 76.261,44.636 ccw(c76.217,45.737) 76.769,44.784 ; 76.261,57.154 76.261,57.592 ; 76.261,57.154 76.699,57.592 ; 76.261,57.592 76.699,57.592 ; 76.261,57.592 76.261,58.1 ; 76.261,58.1 76.261,58.608 ; 76.261,58.1 76.769,58.1 ; 76.261,58.608 pad.@76.261,59.116 ; 76.261,58.608 76.769,58.608 ; pad.@76.261,59.116 76.769,59.116 ; pad.@76.261,59.116 76.261,59.624 ; 76.261,59.624 76.261,60.132 ; 76.261,59.624 76.769,59.624 ; 76.261,60.132 76.769,60.132 ; 76.699,57.592 76.769,57.662 ; 76.769,20.889 77.277,20.889 ; 76.769,20.889 76.769,21.016 ; 76.769,21.016 77.277,21.016 ; 76.769,21.016 pad.@76.769,21.524 ; pad.@76.769,21.524 76.769,22.032 ; pad.@76.769,21.524 77.277,21.524 ; 76.769,22.032 76.769,22.2 ; 76.769,22.032 77.195,22.032 ; 76.769,22.2 77.195,22.2 77.195,22.032 ; 76.769,24.404 76.769,24.572 ; 76.769,24.404 77.195,24.404 77.195,24.572 ; 76.769,24.572 76.769,25.08 ; 76.769,24.572 77.195,24.572 ; 76.769,25.08 77.277,25.08 ; 76.769,25.08 76.769,25.588 ; 76.769,25.588 pad.@76.769,26.096 ; 76.769,25.588 77.277,25.588 ; pad.@76.769,26.096 pad.@76.769,26.223 76.769,26.604 ; pad.@76.769,26.096 77.277,26.096 ; 76.769,26.604 76.769,27.112 ; 76.769,26.604 77.277,26.604 ; 76.769,27.112 76.769,27.62 ; 76.769,27.112 77.277,27.112 ; 76.769,27.62 76.769,28.128 ; 76.769,27.62 77.277,27.62 ; 76.769,28.128 76.769,28.542 ; 76.769,28.128 77.277,28.128 ; 76.769,28.542 77.277,28.542 ; 76.769,39.966 cw(c76.388,38.669) 77.104,39.815 cw(c76.388,38.669) 77.109,39.812 ; 76.769,39.966 76.769,40.32 ; 76.769,40.32 76.769,40.828 ; 76.769,40.32 77.277,40.32 ; 76.769,40.828 76.769,41.336 ; 76.769,40.828 77.277,40.828 ; 76.769,41.336 76.769,41.844 ; 76.769,41.336 77.277,41.336 ; 76.769,41.844 76.769,42.352 ; 76.769,41.844 77.277,41.844 ; 76.769,42.352 76.769,42.86 ; 76.769,42.352 77.277,42.352 ; 76.769,42.86 76.769,43.368 ; 76.769,42.86 77.277,42.86 ; 76.769,43.368 76.769,43.876 ; 76.769,43.368 77.277,43.368 ; 76.769,43.876 76.769,44.384 ; 76.769,43.876 77.277,43.876 ; 76.769,44.384 77.277,44.384 ; 76.769,44.384 76.769,44.784 ; 76.769,44.784 ccw(c76.217,45.737) 76.924,44.892 ; 76.769,44.784 ccw(c76.217,45.737) 76.924,44.892 ; 76.769,57.662 76.769,58.1 ; 76.769,57.662 77.207,58.1 ; 76.769,58.1 77.207,58.1 ; 76.769,58.1 76.769,58.608 ; 76.769,58.608 76.769,59.116 ; 76.769,58.608 77.277,58.608 ; 76.769,59.116 76.769,59.624 ; 76.769,59.116 77.277,59.116 ; 76.769,59.624 76.769,60.132 ; 76.769,59.624 77.277,59.624 ; 76.769,60.132 77.277,60.132 ; 76.924,44.892 ccw(c76.217,45.737) 76.996,44.958 cw(c76.217,45.737) 76.924,44.892 ; 76.924,44.892 77.277,44.892 ; 77.109,39.812 cw(c76.388,38.669) 77.275,39.689 cw(c76.388,38.669) 77.277,39.687 ; 77.109,39.812 77.277,39.812 ; 77.195,22.032 77.195,21.889 77.277,21.889 ; 77.195,24.572 77.195,24.593 77.277,24.593 ; 77.207,58.1 77.277,58.17 ; 77.277,20.889 77.785,20.889 ; 77.277,20.889 77.277,21.016 ; 77.277,21.016 77.785,21.016 ; 77.277,21.016 77.277,21.524 ; 77.277,21.524 77.277,21.889 ; 77.277,21.524 77.785,21.524 ; 77.277,21.889 77.785,21.889 ; 77.277,24.593 77.277,25.08 ; 77.277,24.593 77.785,24.593 ; 77.277,25.08 77.277,25.588 ; 77.277,25.08 77.785,25.08 ; 77.277,25.588 77.277,26.096 ; 77.277,25.588 77.785,25.588 ; 77.277,26.096 77.785,26.096 ; 77.277,26.096 77.277,26.604 ; 77.277,26.604 77.277,27.112 ; 77.277,26.604 77.785,26.604 ; 77.277,27.112 77.277,27.62 ; 77.277,27.112 77.785,27.112 ; 77.277,27.62 77.277,28.128 ; 77.277,27.62 77.785,27.62 ; 77.277,28.128 77.277,28.542 ; 77.277,28.128 77.785,28.128 ; 77.277,28.542 77.785,28.542 ; 77.277,39.687 cw(c76.388,38.669) 77.581,39.304 ; 77.277,39.687 77.277,39.812 ; 77.277,39.812 77.277,40.32 ; 77.277,39.812 77.785,39.812 ; 77.277,40.32 77.277,40.828 ; 77.277,40.32 77.785,40.32 ; 77.277,40.828 77.277,41.336 ; 77.277,40.828 77.785,40.828 ; 77.277,41.336 77.277,41.844 ; 77.277,41.336 77.785,41.336 ; 77.277,41.844 77.277,42.352 ; 77.277,41.844 77.785,41.844 ; 77.277,42.352 77.277,42.86 ; 77.277,42.352 77.785,42.352 ; 77.277,42.86 77.277,43.368 ; 77.277,42.86 77.785,42.86 ; 77.277,43.368 77.277,43.876 ; 77.277,43.368 77.785,43.368 ; 77.277,43.876 77.277,44.384 ; 77.277,43.876 77.785,43.876 ; 77.277,44.384 77.277,44.892 ; 77.277,44.384 77.785,44.384 ; 77.277,44.892 77.277,45.239 ; 77.277,44.892 77.785,44.892 ; 77.277,45.239 77.438,45.4 ; 77.277,58.17 77.715,58.608 ; 77.277,58.17 77.277,58.608 ; 77.277,58.608 77.715,58.608 ; 77.277,58.608 77.277,59.116 ; 77.277,59.116 77.785,59.116 ; 77.277,59.116 77.277,59.624 ; 77.277,59.624 pad.@77.785,59.624 ; 77.277,59.624 77.277,60.132 ; 77.277,60.132 77.785,60.132 ; 77.438,45.4 77.785,45.4 ; 77.438,45.4 77.785,45.747 ; 77.581,39.304 cw(c76.388,38.669) 77.734,38.796 ; 77.581,39.304 77.785,39.304 ; 77.685,38.288 ccw(c76.388,38.669) 77.687,38.296 ccw(c76.388,38.669) 77.734,38.796 ; 77.685,38.288 77.785,38.288 ; 77.715,58.608 77.785,58.678 ; 77.734,38.796 77.785,38.796 ; 77.785,20.889 77.785,21.016 ; 77.785,20.889 78.293,20.889 ; 77.785,21.016 77.785,21.524 ; 77.785,21.016 78.293,21.016 ; 77.785,21.524 77.785,21.889 ; 77.785,21.524 78.293,21.524 ; 77.785,21.889 78.293,21.889 ; 77.785,24.593 78.293,24.593 ; 77.785,24.593 77.785,25.08 ; 77.785,25.08 78.293,25.08 ; 77.785,25.08 77.785,25.588 ; 77.785,25.588 77.785,26.096 ; 77.785,25.588 78.293,25.588 ; 77.785,26.096 78.293,26.096 ; 77.785,26.096 77.785,26.604 ; 77.785,26.604 77.785,27.112 ; 77.785,26.604 78.293,26.604 ; 77.785,27.112 77.785,27.62 ; 77.785,27.112 78.293,27.112 ; 77.785,27.62 77.785,28.128 ; 77.785,27.62 78.293,27.62 ; 77.785,28.128 77.785,28.542 ; 77.785,28.128 78.293,28.128 ; 77.785,28.542 78.293,28.542 ; 77.785,38.004 CN1.1@78.293,38.004 ; 77.785,38.004 77.785,38.288 ; 77.785,38.288 77.785,38.796 ; 77.785,38.288 CN1.1@78.293,38.288 ; 77.785,38.796 77.785,39.304 ; 77.785,38.796 CN1.1@78.293,38.796 ; 77.785,39.304 77.785,39.812 ; 77.785,39.304 CN1.1@78.293,39.304 ; 77.785,39.812 77.785,40.32 ; 77.785,39.812 78.293,39.812 ; 77.785,40.32 77.785,40.828 ; 77.785,40.32 78.293,40.32 ; 77.785,40.828 77.785,41.336 ; 77.785,40.828 78.293,40.828 ; 77.785,41.336 77.785,41.844 ; 77.785,41.336 78.293,41.336 ; 77.785,41.844 77.785,42.352 ; 77.785,41.844 78.293,41.844 ; 77.785,42.352 77.785,42.86 ; 77.785,42.352 78.293,42.352 ; 77.785,42.86 77.785,43.368 ; 77.785,42.86 78.293,42.86 ; 77.785,43.368 77.785,43.876 ; 77.785,43.368 78.293,43.368 ; 77.785,43.876 77.785,44.384 ; 77.785,43.876 78.293,43.876 ; 77.785,44.384 78.293,44.384 ; 77.785,44.384 77.785,44.892 ; 77.785,44.892 78.293,44.892 ; 77.785,44.892 77.785,45.4 ; 77.785,45.4 77.785,45.747 ; 77.785,45.4 78.293,45.4 ; 77.785,45.747 77.946,45.908 ; 77.785,58.678 78.223,59.116 ; 77.785,58.678 77.785,59.116 ; 77.785,59.116 pad.@77.785,59.624 ; 77.785,59.116 78.223,59.116 ; pad.@77.785,59.624 78.293,59.624 ; pad.@77.785,59.624 77.785,60.132 ; 77.785,60.132 78.293,60.132 ; 77.946,45.908 78.293,46.255 ; 77.946,45.908 78.293,45.908 ; 78.152,52.004 78.293,52.004 ; 78.152,52.004 78.152,52.512 ; 78.152,52.004 78.152,51.897 78.293,51.756 ; 78.152,52.512 78.152,53.02 ; 78.152,52.512 78.293,52.512 ; 78.152,53.02 78.293,53.02 ; 78.152,53.02 78.152,53.528 ; 78.152,53.528 78.293,53.528 ; 78.152,53.528 78.152,54.036 ; 78.152,54.036 78.293,54.036 ; 78.152,54.036 78.152,54.544 ; 78.152,54.544 78.152,55.052 ; 78.152,54.544 78.293,54.544 ; 78.152,55.052 78.293,55.052 ; 78.152,55.052 78.152,55.222 78.293,55.363 ; 78.223,59.116 78.293,59.186 ; 78.293,20.889 78.293,21.016 ; 78.293,20.889 78.801,20.889 ; 78.293,21.016 78.293,21.524 ; 78.293,21.016 78.801,21.016 ; 78.293,21.524 78.293,21.889 ; 78.293,21.524 78.801,21.524 ; 78.293,21.889 78.801,21.889 ; 78.293,24.593 78.293,25.08 ; 78.293,24.593 78.801,24.593 ; 78.293,25.08 78.293,25.588 ; 78.293,25.08 78.801,25.08 ; 78.293,25.588 78.293,26.096 ; 78.293,25.588 78.801,25.588 ; 78.293,26.096 78.293,26.604 ; 78.293,26.096 78.801,26.096 ; 78.293,26.604 78.293,27.112 ; 78.293,26.604 78.801,26.604 ; 78.293,27.112 78.293,27.62 ; 78.293,27.112 78.801,27.112 ; 78.293,27.62 78.293,28.128 ; 78.293,27.62 78.801,27.62 ; 78.293,28.128 78.293,28.542 ; 78.293,28.128 78.801,28.128 ; 78.293,28.542 78.454,28.542 ; CN1.1@78.293,38.004 CN1.1@78.801,38.004 ; CN1.1@78.293,38.004 CN1.1@78.293,38.288 ; CN1.1@78.293,38.288 CN1.1@78.801,38.288 ; CN1.1@78.293,38.288 CN1.1@78.293,38.796 ; CN1.1@78.293,38.796 CN1.1@78.293,39.304 ; CN1.1@78.293,38.796 CN1.1@78.801,38.796 ; CN1.1@78.293,39.304 78.293,39.812 ; CN1.1@78.293,39.304 CN1.1@78.801,39.304 ; 78.293,39.812 78.293,40.32 ; 78.293,39.812 78.801,39.812 ; 78.293,40.32 78.293,40.828 ; 78.293,40.32 78.801,40.32 ; 78.293,40.828 78.293,41.336 ; 78.293,40.828 78.801,40.828 ; 78.293,41.336 78.293,41.844 ; 78.293,41.336 78.801,41.336 ; 78.293,41.844 78.293,42.352 ; 78.293,41.844 78.801,41.844 ; 78.293,42.352 78.293,42.86 ; 78.293,42.352 78.801,42.352 ; 78.293,42.86 78.293,43.368 ; 78.293,42.86 78.801,42.86 ; 78.293,43.368 78.293,43.876 ; 78.293,43.368 78.801,43.368 ; 78.293,43.876 78.293,44.384 ; 78.293,43.876 78.801,43.876 ; 78.293,44.384 78.293,44.892 ; 78.293,44.384 78.801,44.384 ; 78.293,44.892 78.801,44.892 ; 78.293,44.892 78.293,45.4 ; 78.293,45.4 78.293,45.908 ; 78.293,45.4 78.801,45.4 ; 78.293,45.908 78.293,46.255 ; 78.293,45.908 78.801,45.908 ; 78.293,51.756 78.293,52.004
